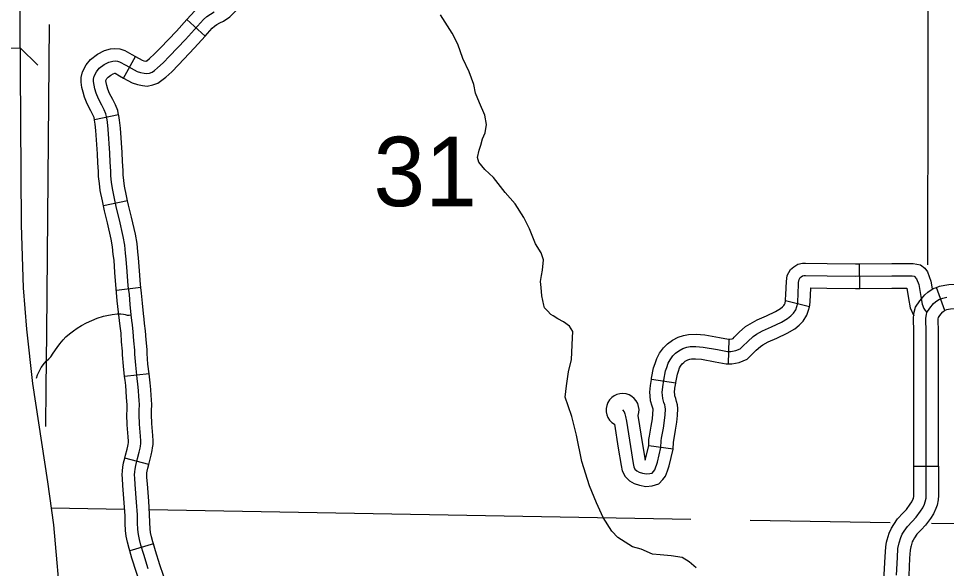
# Model space of a CAD drawing. Extents: x 670147 to 673275, y 705573 to 707613.
# Drawn here: x 671930 to 672042.9, y 706425.4 to 706492.4 of the extents above; entities that cross this region are included whole.
import ezdxf

# ---------------------------------------------------------------- set-up
doc = ezdxf.new("R2010")
doc.units = 0
for name, color, linetype in [('10', 7, 'Continuous'), ('31', 7, 'Continuous'), ('32', 7, 'Continuous'), ('35', 7, 'Continuous'), ('37', 7, 'Continuous'), ('4', 7, 'Continuous'), ('5', 7, 'Continuous')]:
    doc.layers.add(name, color=color, linetype=linetype)

msp = doc.modelspace()

# ---------------------------------------------------------------- linework, layer by layer
at = {"layer": '10'}
for points in [[(671930.16, 706488.8), (671930.16, 706489.12), (671930.13, 706499.79)], [(671925.16, 706488.79), (671930.16, 706488.8), (671930.17, 706486.14), (671930.29, 706467.26), (671930.53, 706459.61), (671930.91, 706454.57), (671931.66, 706447.96), (671933.49, 706436.01), (671934.22, 706430.74), (671935.13, 706420.14), (671935.22, 706403.69), (671935.02, 706391.71), (671934.8, 706379.03), (671934.76, 706376.46), (671935.03, 706373.49), (671937.35, 706366.83), (671941.13, 706356.87), (671942.59, 706352.12), (671944.27, 706343.33), (671945.71, 706333.86), (671947.06, 706323.36), (671947.64, 706307.92), (671948.19, 706298.41)]]:
    msp.add_lwpolyline(points, dxfattribs=at)
at = {"layer": '31'}
for p, q in [((672042.67, 706456.85), (672041.63, 706459.66)), ((672041.63, 706459.66), (672041.63, 706459.66)), ((672038.89, 706437.89), (672041.89, 706437.9))]:
    msp.add_line(p, q, dxfattribs=at)
for points in [[(672041.63, 706459.66), (672042.02, 706459.8), (672042.67, 706459.94), (672043.14, 706459.99), (672044.45, 706460.03), (672046.25, 706460.13), (672049.43, 706460.21), (672049.82, 706460.25), (672049.95, 706460.27), (672050.09, 706460.38), (672050.19, 706460.49), (672050.26, 706460.62), (672050.3, 706460.69), (672050.31, 706460.73), (672050.31, 706460.73)], [(672053.27, 706460.25), (672053.26, 706460.16), (672053.14, 706459.65), (672052.87, 706459.13), (672052.62, 706458.73), (672052.18, 706458.21), (672051.43, 706457.62), (672050.89, 706457.39), (672050.22, 706457.27), (672049.62, 706457.21), (672046.37, 706457.13), (672044.59, 706457.03), (672043.34, 706456.99), (672043.12, 706456.97), (672042.85, 706456.91), (672042.67, 706456.85)], [(672038.9, 706448.46), (672038.9, 706450.2), (672038.88, 706454.17), (672038.86, 706456), (672038.93, 706456.63), (672039.1, 706457.23), (672039.61, 706458.02), (672040.22, 706458.76), (672040.6, 706459.09), (672041.24, 706459.52), (672041.63, 706459.66)], [(672036.79, 706424.65), (672036.89, 706426.8), (672036.96, 706427.88), (672037.09, 706428.57), (672037.29, 706429.22), (672037.48, 706429.62), (672037.71, 706429.98), (672038.1, 706430.56), (672038.67, 706431.16), (672039.16, 706431.68), (672039.68, 706432.4), (672039.97, 706432.82), (672040.17, 706433.28), (672040.27, 706433.57), (672040.37, 706434.01), (672040.4, 706434.37), (672040.37, 706442.59), (672040.4, 706450.21), (672040.38, 706454.18), (672040.36, 706455.92), (672040.41, 706456.34), (672040.48, 706456.61), (672040.82, 706457.13), (672041.3, 706457.71), (672041.51, 706457.9), (672041.93, 706458.17), (672042.43, 706458.36), (672042.89, 706458.45)], [(672041.9, 706448.45), (672041.9, 706450.21), (672041.88, 706454.2), (672041.86, 706455.84), (672041.88, 706456), (672042.04, 706456.25), (672042.37, 706456.66), (672042.42, 706456.7), (672042.61, 706456.83), (672042.67, 706456.85)], [(672038.89, 706437.89), (672038.87, 706442.59), (672038.9, 706448.46)], [(672041.89, 706437.9), (672041.87, 706442.59), (672041.9, 706448.45)], [(672035.57, 706428.63), (672035.63, 706428.93), (672035.89, 706429.76), (672036.16, 706430.34), (672036.45, 706430.8), (672036.92, 706431.5), (672037.59, 706432.2), (672038.01, 706432.64), (672038.46, 706433.26), (672038.65, 706433.55), (672038.78, 706433.83), (672038.83, 706433.98), (672038.89, 706434.24), (672038.9, 706434.43), (672038.89, 706437.89)], [(672041.89, 706437.9), (672041.9, 706434.32), (672041.86, 706433.79), (672041.72, 706433.15), (672041.57, 706432.73), (672041.29, 706432.08), (672040.91, 706431.53), (672040.32, 706430.72), (672039.76, 706430.13), (672039.27, 706429.61), (672038.96, 706429.16), (672038.8, 706428.9), (672038.69, 706428.68), (672038.55, 706428.21), (672038.52, 706428.07)], [(672033.97, 706418.71), (672034.27, 706419.35), (672034.59, 706420.21), (672034.79, 706420.92), (672035.07, 706422.01), (672035.18, 706422.64), (672035.22, 706423.12), (672035.29, 706424.72), (672035.39, 706426.88), (672035.47, 706428.07), (672035.57, 706428.63)], [(672038.52, 706428.07), (672038.45, 706427.69), (672038.38, 706426.71), (672038.28, 706424.58), (672038.21, 706422.94), (672038.16, 706422.27), (672038.01, 706421.38), (672037.69, 706420.15), (672037.45, 706419.28), (672037.03, 706418.17), (672036.65, 706417.38), (672036.63, 706417.34)]]:
    msp.add_lwpolyline(points, dxfattribs=at)
at = {"layer": '32'}
for p, q in [((671952.67, 706490.24), (671950.44, 706492.25)), ((671942.72, 706485.14), (671944.17, 706487.77)), ((671942.13, 706480.67), (671939.19, 706480.05)), ((671943.23, 706470.17), (671940.29, 706469.59)), ((672032.32, 706459.53), (672032.29, 706462.53)), ((671944.84, 706459.66), (671941.86, 706459.28)), ((672026.19, 706457.28), (672023.29, 706458.02)), ((672016.35, 706450.37), (672016.42, 706453.36)), ((671945.84, 706449.13), (671942.86, 706448.79)), ((672009.91, 706447.98), (672006.95, 706448.44)), ((672009.62, 706439.96), (672006.63, 706440.37)), ((671945.79, 706438.09), (671942.89, 706438.87)), ((671946.37, 706428.44), (671943.5, 706427.58))]:
    msp.add_line(p, q, dxfattribs=at)
for points in [[(671950.44, 706492.25), (671951.39, 706493.31), (671951.92, 706493.8), (671952.52, 706494.2), (671953.06, 706494.51), (671953.39, 706494.66), (671953.74, 706494.9), (671954.04, 706495.21), (671954.13, 706495.36), (671954.18, 706495.5), (671954.36, 706496.1), (671954.66, 706497.25), (671954.96, 706498.07), (671955.36, 706498.77), (671955.7, 706499.34), (671956.16, 706499.99), (671956.51, 706500.39)], [(671952.67, 706490.24), (671953.53, 706491.2), (671953.78, 706491.43), (671954.1, 706491.64), (671954.46, 706491.85), (671954.89, 706492.05), (671955.68, 706492.6), (671956.38, 706493.32), (671956.87, 706494.04), (671957.04, 706494.61), (671957.25, 706495.28), (671957.53, 706496.36), (671957.69, 706496.8), (671957.96, 706497.27), (671958.21, 706497.7), (671958.52, 706498.13), (671958.79, 706498.44)], [(671942, 706487.2), (671942.26, 706487.12), (671943, 706486.7), (671944.38, 706485.94), (671944.81, 706485.79), (671945.25, 706485.71), (671945.55, 706485.68), (671945.88, 706485.74), (671946.21, 706485.86), (671946.48, 706486.05), (671946.87, 706486.38), (671947.55, 706486.99), (671948.31, 706487.79), (671950.27, 706489.82), (671952.46, 706492.26), (671952.85, 706492.62), (671953.31, 706492.92), (671953.76, 706493.18)], [(671944.17, 706487.77), (671944.99, 706487.32), (671945.2, 706487.24), (671945.46, 706487.19), (671945.47, 706487.19), (671945.52, 706487.21), (671945.57, 706487.24), (671945.89, 706487.51), (671946.51, 706488.07), (671947.23, 706488.83), (671949.17, 706490.84), (671950.44, 706492.25)], [(671942.72, 706485.14), (671943.78, 706484.56), (671944.43, 706484.34), (671945.03, 706484.22), (671945.62, 706484.16), (671946.28, 706484.29), (671946.91, 706484.52), (671947.4, 706484.86), (671947.86, 706485.25), (671948.6, 706485.91), (671949.4, 706486.75), (671951.37, 706488.8), (671952.67, 706490.24)], [(671939.19, 706480.05), (671939.14, 706480.33), (671939.01, 706480.65), (671938.76, 706481.14), (671938.3, 706482), (671937.99, 706482.8), (671937.8, 706483.42), (671937.67, 706483.98), (671937.56, 706484.63), (671937.59, 706485.21), (671937.75, 706485.91), (671938.2, 706486.74), (671938.72, 706487.4), (671939.55, 706488.04), (671940.42, 706488.49), (671941.16, 706488.67), (671941.68, 706488.72), (671942.28, 706488.69), (671942.88, 706488.49), (671943.73, 706488.01), (671944.17, 706487.77)], [(671944.65, 706444.72), (671944.66, 706445.36), (671944.65, 706445.92), (671944.6, 706446.38), (671944.55, 706447.12), (671944.49, 706447.87), (671944.4, 706448.56), (671944.21, 706450.19), (671944.12, 706451.53), (671944.1, 706452), (671944, 706453.16), (671943.92, 706454.23), (671943.81, 706455.1), (671943.76, 706455.63), (671943.68, 706456.32), (671943.54, 706457.59), (671943.44, 706458.8), (671943.3, 706459.86), (671943.17, 706461.57), (671943.07, 706463.11), (671942.98, 706463.81), (671942.88, 706464.79), (671942.69, 706465.83), (671942.26, 706467.86), (671941.87, 706469.31), (671941.64, 706470.48), (671941.37, 706471.71), (671941.28, 706472.47), (671941.18, 706473.25), (671941.18, 706473.81), (671941.1, 706474.88), (671941.07, 706475.99), (671940.88, 706478.9), (671940.78, 706479.77), (671940.68, 706480.29), (671940.58, 706480.76), (671940.37, 706481.27), (671940.09, 706481.83), (671939.67, 706482.62), (671939.41, 706483.29), (671939.25, 706483.82), (671939.14, 706484.28), (671939.06, 706484.71), (671939.08, 706485), (671939.16, 706485.38), (671939.45, 706485.91), (671939.78, 706486.33), (671940.36, 706486.77), (671940.95, 706487.08), (671941.41, 706487.19), (671941.72, 706487.22), (671942, 706487.2)], [(671942.13, 706480.67), (671942.02, 706481.2), (671941.74, 706481.89), (671941.42, 706482.52), (671941.04, 706483.25), (671940.83, 706483.77), (671940.7, 706484.22), (671940.61, 706484.59), (671940.57, 706484.8), (671940.58, 706484.84), (671940.71, 706485.08), (671940.85, 706485.25), (671941.17, 706485.5), (671941.48, 706485.66), (671941.67, 706485.71), (671941.7, 706485.71), (671942.26, 706485.39), (671942.72, 706485.14)], [(671943.23, 706470.17), (671943.11, 706470.79), (671942.85, 706471.96), (671942.77, 706472.65), (671942.68, 706473.35), (671942.68, 706473.87), (671942.59, 706474.96), (671942.57, 706476.06), (671942.37, 706479.04), (671942.26, 706480), (671942.15, 706480.59), (671942.13, 706480.67)], [(671940.29, 706469.59), (671940.18, 706470.17), (671939.89, 706471.46), (671939.79, 706472.29), (671939.68, 706473.15), (671939.68, 706473.75), (671939.6, 706474.8), (671939.57, 706475.92), (671939.38, 706478.77), (671939.3, 706479.54), (671939.21, 706479.99), (671939.19, 706480.05)], [(671944.84, 706459.66), (671944.79, 706460.02), (671944.67, 706461.68), (671944.56, 706463.26), (671944.47, 706463.98), (671944.37, 706465), (671944.17, 706466.12), (671943.72, 706468.21), (671943.34, 706469.65), (671943.23, 706470.17)], [(671941.94, 706458.01), (671941.67, 706461.47), (671941.58, 706462.97), (671941.49, 706463.64), (671941.4, 706464.58), (671941.22, 706465.54), (671940.8, 706467.51), (671940.41, 706468.98), (671940.29, 706469.59)], [(672023.27, 706457.96), (672023.29, 706458.15), (672023.31, 706458.78), (672023.38, 706460.36), (672023.47, 706461.12), (672023.89, 706461.82), (672024.28, 706462.15), (672024.77, 706462.47), (672025.34, 706462.59), (672025.72, 706462.59), (672028.35, 706462.56), (672031.8, 706462.53), (672032.29, 706462.53)], [(672032.29, 706462.53), (672036.2, 706462.56), (672038.82, 706462.55), (672039.7, 706462.39), (672040.22, 706462), (672040.57, 706461.55), (672040.94, 706460.42), (672041.1, 706459.46)], [(672012.38, 706452.47), (672013.24, 706452.4), (672014.98, 706452.08), (672016.2, 706451.87), (672016.64, 706451.86), (672017.22, 706451.96), (672017.75, 706452.18), (672018.09, 706452.52), (672018.67, 706453.09), (672019.32, 706453.67), (672019.76, 706453.95), (672020.48, 706454.35), (672021.57, 706454.84), (672022.78, 706455.41), (672023.52, 706455.85), (672023.92, 706456.19), (672024.25, 706456.5), (672024.52, 706456.93), (672024.65, 706457.31), (672024.76, 706457.72), (672024.79, 706458.07), (672024.8, 706458.72), (672024.87, 706460.24), (672024.92, 706460.62), (672025.05, 706460.84), (672025.18, 706460.95), (672025.35, 706461.06), (672025.49, 706461.09), (672025.71, 706461.09), (672028.33, 706461.06), (672031.79, 706461.03), (672036.2, 706461.06), (672038.67, 706461.05), (672038.91, 706461.01), (672039.22, 706460.7), (672039.49, 706460.02), (672039.72, 706458.55), (672039.9, 706457.6), (672040.12, 706457.08), (672040.27, 706456.85), (672040.48, 706456.61)], [(671945.84, 706449.13), (671945.7, 706450.32), (671945.62, 706451.61), (671945.6, 706452.1), (671945.49, 706453.28), (671945.41, 706454.37), (671945.3, 706455.26), (671945.25, 706455.79), (671945.17, 706456.49), (671945.03, 706457.74), (671944.93, 706458.96), (671944.84, 706459.66)], [(672026.19, 706457.28), (672026.24, 706457.47), (672026.28, 706457.98), (672026.3, 706458.67), (672026.34, 706459.59), (672028.31, 706459.56), (672031.79, 706459.53), (672032.32, 706459.53)], [(672032.32, 706459.53), (672036.21, 706459.56), (672038.04, 706459.56), (672038.25, 706458.3), (672038.45, 706457.16), (672038.88, 706456.18)], [(671942.86, 706448.79), (671942.71, 706450.05), (671942.62, 706451.44), (671942.6, 706451.9), (671942.5, 706453.04), (671942.43, 706454.08), (671942.32, 706454.94), (671941.94, 706458.01)], [(672016.42, 706453.36), (672016.52, 706453.36), (672016.8, 706453.41), (672016.89, 706453.45), (672017.03, 706453.59), (672017.64, 706454.19), (672018.42, 706454.88), (672018.99, 706455.24), (672019.81, 706455.7), (672020.95, 706456.2), (672022.07, 706456.73), (672022.66, 706457.08), (672022.92, 706457.3), (672023.08, 706457.46), (672023.16, 706457.59), (672023.22, 706457.74), (672023.29, 706458.02)], [(672016.35, 706450.37), (672016.75, 706450.36), (672017.65, 706450.52), (672018.6, 706450.91), (672019.14, 706451.46), (672019.69, 706452), (672020.22, 706452.47), (672020.53, 706452.66), (672021.16, 706453.01), (672022.2, 706453.47), (672023.48, 706454.08), (672024.39, 706454.63), (672024.93, 706455.07), (672025.42, 706455.55), (672025.88, 706456.27), (672026.09, 706456.87), (672026.19, 706457.28)], [(671932.15, 706448.61), (671932.27, 706449.03), (671932.42, 706449.34), (671932.71, 706449.9), (671933.1, 706450.42), (671933.33, 706450.66), (671933.65, 706450.95), (671933.87, 706451.2), (671934.19, 706451.65), (671934.65, 706452.35), (671934.99, 706452.8), (671935.38, 706453.27), (671935.72, 706453.62), (671936.15, 706454.02), (671936.63, 706454.38), (671937.07, 706454.68), (671937.61, 706455), (671938.22, 706455.33), (671938.86, 706455.62), (671939.54, 706455.89), (671940.29, 706456.14), (671940.7, 706456.25), (671941.35, 706456.37), (671941.95, 706456.42), (671942.42, 706456.43), (671942.73, 706456.41), (671942.93, 706456.35), (671943.19, 706456.29), (671943.41, 706456.28), (671943.68, 706456.32)], [(672006.95, 706448.44), (672006.97, 706448.62), (672007.23, 706449.86), (672007.41, 706450.4), (672007.63, 706451.02), (672007.94, 706451.64), (672008.41, 706452.28), (672008.91, 706452.8), (672009.52, 706453.24), (672010.21, 706453.59), (672010.88, 706453.82), (672011.49, 706453.94), (672012.41, 706453.98), (672013.44, 706453.89), (672015.24, 706453.55), (672016.34, 706453.37), (672016.42, 706453.36)], [(672008.12, 706440.16), (672008.15, 706440.97), (672008.2, 706441.29), (672008.42, 706442.53), (672008.57, 706443.46), (672008.65, 706444.15), (672008.67, 706444.84), (672008.64, 706445.1), (672008.58, 706445.36), (672008.48, 706445.66), (672008.34, 706446.13), (672008.29, 706446.55), (672008.28, 706446.88), (672008.33, 706447.57), (672008.45, 706448.35), (672008.69, 706449.48), (672008.83, 706449.92), (672009.01, 706450.43), (672009.22, 706450.85), (672009.56, 706451.31), (672009.9, 706451.67), (672010.3, 706451.95), (672010.8, 706452.21), (672011.27, 706452.37), (672011.66, 706452.45), (672012.38, 706452.47)], [(672009.91, 706447.98), (672009.93, 706448.08), (672010.14, 706449.09), (672010.25, 706449.45), (672010.39, 706449.85), (672010.5, 706450.06), (672010.71, 706450.34), (672010.89, 706450.53), (672011.08, 706450.67), (672011.39, 706450.83), (672011.65, 706450.92), (672011.84, 706450.95), (672012.34, 706450.97), (672013.04, 706450.91), (672014.71, 706450.6), (672016.06, 706450.37), (672016.35, 706450.37)], [(671942.89, 706438.87), (671942.98, 706439.22), (671943.18, 706439.96), (671943.27, 706440.34), (671943.3, 706440.52), (671943.32, 706440.76), (671943.33, 706440.96), (671943.31, 706441.45), (671943.19, 706442.93), (671943.14, 706444.17), (671943.16, 706444.75), (671943.16, 706445.35), (671943.15, 706445.82), (671943.1, 706446.26), (671943.06, 706447.01), (671943, 706447.7), (671942.91, 706448.38), (671942.86, 706448.79)], [(671945.79, 706438.09), (671945.88, 706438.44), (671946.1, 706439.24), (671946.23, 706439.8), (671946.27, 706440.14), (671946.32, 706440.55), (671946.33, 706440.97), (671946.31, 706441.62), (671946.19, 706443.11), (671946.14, 706444.19), (671946.15, 706444.69), (671946.16, 706445.38), (671946.15, 706446.02), (671946.09, 706446.51), (671946.05, 706447.22), (671945.98, 706448.03), (671945.88, 706448.75), (671945.84, 706449.13)], [(672006.2, 706438.61), (672006.63, 706440.37), (672006.65, 706441.13), (672006.73, 706441.56), (672006.94, 706442.78), (672007.09, 706443.66), (672007.15, 706444.25), (672007.17, 706444.78), (672007.16, 706444.85), (672007.14, 706444.95), (672007.05, 706445.2), (672006.86, 706445.83), (672006.79, 706446.44), (672006.78, 706446.91), (672006.83, 706447.73), (672006.95, 706448.44)], [(672008.91, 706437.34), (672009.12, 706437.95), (672009.62, 706439.96), (672009.64, 706440.82), (672009.68, 706441.03), (672009.9, 706442.28), (672010.06, 706443.25), (672010.15, 706444.05), (672010.17, 706444.91), (672010.12, 706445.35), (672010.03, 706445.76), (672009.91, 706446.12), (672009.81, 706446.44), (672009.79, 706446.66), (672009.78, 706446.85), (672009.82, 706447.4), (672009.91, 706447.98)], [(671945.74, 706425.42), (671945.2, 706427.14), (671944.85, 706428.28), (671944.68, 706428.97), (671944.55, 706429.59), (671944.49, 706430.18), (671944.45, 706430.99), (671944.42, 706431.96), (671944.29, 706433.53), (671944.13, 706435.66), (671944.09, 706436.45), (671944.08, 706436.85), (671944.09, 706437.22), (671944.13, 706437.53), (671944.21, 706437.99), (671944.43, 706438.83), (671944.64, 706439.6), (671944.75, 706440.07), (671944.78, 706440.33), (671944.82, 706440.66), (671944.83, 706440.97), (671944.81, 706441.53), (671944.69, 706443.02), (671944.64, 706444.18), (671944.65, 706444.72)], [(672003.45, 706444.74), (672003.63, 706444.52), (672003.73, 706444.27), (672003.82, 706443.95), (672003.91, 706443.38), (672004.41, 706440.31), (672004.74, 706438.24), (672004.81, 706437.83), (672004.96, 706437.55), (672005.19, 706437.32), (672005.47, 706437.17), (672005.88, 706437.05), (672006.37, 706436.95), (672006.78, 706436.99), (672007.03, 706437.06), (672007.2, 706437.24), (672007.36, 706437.44), (672007.68, 706438.37), (672008.12, 706440.16)], [(672005.32, 706444.05), (672005.89, 706440.54), (672006.2, 706438.61)], [(672002.45, 706443), (672002.92, 706440.07), (672003.26, 706437.98), (672003.38, 706437.33), (672003.75, 706436.65), (672004.28, 706436.11), (672004.88, 706435.78), (672005.52, 706435.59), (672006.29, 706435.44), (672007.06, 706435.51), (672007.85, 706435.74), (672008.33, 706436.26), (672008.69, 706436.7), (672008.91, 706437.34)], [(671943.5, 706427.58), (671943.4, 706427.88), (671943.21, 706428.63), (671943.06, 706429.36), (671942.99, 706430.07), (671942.95, 706430.92), (671942.92, 706431.87), (671942.8, 706433.42), (671942.63, 706435.56), (671942.59, 706436.4), (671942.58, 706436.85), (671942.59, 706437.34), (671942.65, 706437.76), (671942.74, 706438.31), (671942.89, 706438.87)], [(671946.37, 706428.44), (671946.3, 706428.68), (671946.14, 706429.3), (671946.03, 706429.81), (671945.99, 706430.28), (671945.95, 706431.05), (671945.91, 706432.04), (671945.79, 706433.65), (671945.63, 706435.76), (671945.58, 706436.51), (671945.58, 706436.85), (671945.58, 706437.1), (671945.61, 706437.3), (671945.67, 706437.67), (671945.79, 706438.09)], [(671946.51, 706417.24), (671946.57, 706417.37), (671947.1, 706418.78), (671947.55, 706420.12), (671947.8, 706420.99), (671947.87, 706421.31), (671947.93, 706421.62), (671947.97, 706421.99), (671947.96, 706422.52), (671947.89, 706423.19), (671947.78, 706423.85), (671947.59, 706424.61), (671947.16, 706425.89), (671946.63, 706427.58), (671946.37, 706428.44)], [(671943.8, 706418.53), (671943.81, 706418.55), (671944.27, 706419.78), (671944.69, 706421.02), (671944.89, 706421.72), (671944.92, 706421.87), (671944.96, 706422.07), (671944.97, 706422.15), (671944.96, 706422.34), (671944.92, 706422.79), (671944.84, 706423.24), (671944.71, 706423.77), (671944.31, 706424.95), (671943.76, 706426.69), (671943.5, 706427.58)]]:
    msp.add_lwpolyline(points, dxfattribs=at)
msp.add_arc((672003.45, 706444.74), 2, 339.7997, 240.2084, dxfattribs=at)
at = {"layer": '35'}
msp.add_lwpolyline([(672012.4, 706425.54), (672011.57, 706426.25), (672010.68, 706426.78), (672009.35, 706427), (672008.03, 706427.09), (672007.1, 706427.18), (672005.72, 706427.8), (672004.66, 706428.06), (672002.89, 706429.21), (672002.14, 706429.97), (672001.07, 706431.65), (672000.28, 706433.42), (671999.43, 706435.5), (671998.5, 706438.47), (671997.84, 706441.66), (671997.26, 706443.96), (671996.82, 706445.25), (671996.47, 706446.31), (671996.64, 706447.69), (671996.87, 706449.37), (671997.22, 706450.87), (671997.35, 706453.53), (671997.4, 706454.28), (671997, 706454.95), (671996.25, 706455.48), (671995.58, 706455.83), (671995.01, 706456.19), (671994.74, 706456.36), (671994.3, 706456.81), (671993.94, 706457.16), (671993.86, 706457.51), (671993.63, 706458.64), (671993.55, 706459.65), (671993.46, 706460.36), (671993.59, 706461.12), (671993.72, 706461.74), (671993.81, 706463.02), (671993.55, 706463.86), (671992.84, 706464.97), (671992.13, 706466.79), (671991.42, 706468.16), (671990.4, 706469.84), (671989.16, 706471.22), (671987.74, 706473.03), (671986.68, 706474.01), (671985.97, 706474.89), (671985.8, 706475.47), (671986.02, 706476.35), (671986.19, 706476.97), (671986.42, 706477.73), (671986.73, 706478.48), (671986.9, 706479.5), (671986.68, 706480.61), (671986.06, 706482.11), (671985.55, 706483.31), (671985.35, 706484.33), (671984.8, 706485.88), (671984.02, 706487.52), (671983.4, 706489.24), (671982.7, 706490.58), (671981.3, 706492.81)], dxfattribs=at)
at = {"layer": '37'}
msp.add_lwpolyline([(671930.16, 706488.8), (671932.29, 706486.69)], dxfattribs=at)
at = {"layer": '4'}
for points in [[(671933.67, 706491.66), (671933.34, 706454.11), (671933.28, 706447.45)], [(671933.28, 706447.45), (671933.24, 706442.72)], [(671942.86, 706432.64), (671933.93, 706432.8)], [(672011.74, 706431.41), (671945.87, 706432.58)], [(672036, 706430.98), (672018.96, 706431.28)], [(672079.4, 706430.36), (672041.04, 706430.9)]]:
    msp.add_lwpolyline(points, dxfattribs=at)
at = {"layer": '5'}
msp.add_lwpolyline([(672040.63, 706506.26), (672040.56, 706462.42)], dxfattribs=at)

# ---------------------------------------------------------------- texts
msp.add_text('31', height=8.448, dxfattribs=at).set_placement((671973.14, 706469.54))

doc.saveas('drawing.dxf')
